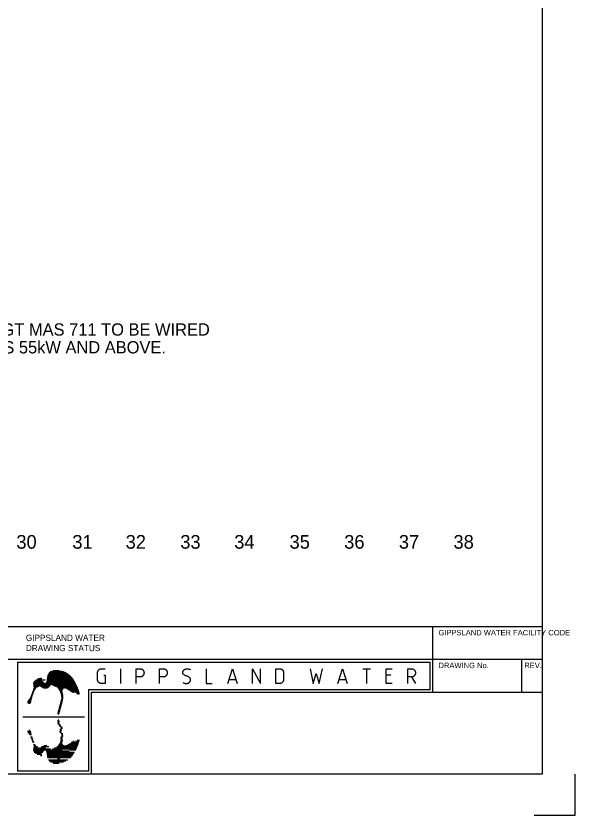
# Model space of a CAD drawing. Extents: x 0 to 841, y 0 to 594.
# Drawn here: x 636.4 to 841, y 0 to 292.5 of the extents above; entities that cross this region are included whole.
import ezdxf

# ---------------------------------------------------------------- set-up
doc = ezdxf.new("R2010")
doc.units = 0
doc.layers.add('A1BORDER', color=7, linetype='Continuous')
doc.layers.add('Level 1', color=7, linetype='Continuous')

msp = doc.modelspace()

# ---------------------------------------------------------------- linework, layer by layer
at = {"layer": 'A1BORDER'}
for p, q in [((829, 581), (829, 15)), ((592.5, 69), (829, 69)), ((789, 45), (789, 69)), ((28, 57), (829, 57)), ((637, 56), (788, 56)), ((637, 56), (637, 16)), ((788, 46), (788, 56)), ((821.5, 45), (821.5, 57)), ((649.39, 52.72), (653.15, 52.72)), ((650.01, 52.92), (652.2, 52.92)), ((644.54, 49.92), (645.36, 49.92)), ((645.37, 50.12), (645.86, 50.12)), ((647.75, 49.92), (657.17, 49.92)), ((647.78, 50.12), (657.02, 50.12)), ((647.81, 50.32), (656.86, 50.32)), ((647.85, 50.52), (656.69, 50.52)), ((647.88, 50.72), (656.5, 50.72)), ((647.91, 50.92), (656.3, 50.92)), ((647.96, 51.12), (656.08, 51.12)), ((648.03, 51.32), (655.85, 51.32)), ((648.12, 51.52), (655.59, 51.52)), ((648.23, 51.72), (655.31, 51.72)), ((648.37, 51.92), (655, 51.92)), ((648.53, 52.12), (654.64, 52.12)), ((648.74, 52.32), (654.24, 52.32)), ((649.02, 52.52), (653.76, 52.52)), ((642.73, 48.12), (658.25, 48.12)), ((642.74, 47.92), (658.35, 47.92)), ((642.75, 48.32), (646.79, 48.32)), ((642.79, 47.72), (649.08, 47.72)), ((642.81, 48.52), (646.55, 48.52)), ((642.83, 47.52), (648.95, 47.52)), ((642.85, 47.31), (644.88, 47.31)), ((642.87, 47.12), (644.57, 47.12)), ((642.88, 46.92), (644.23, 46.92)), ((642.9, 48.72), (646.37, 48.72)), ((643.04, 48.92), (646.16, 48.92)), ((643.26, 49.12), (645.9, 49.12)), ((643.54, 49.32), (645.57, 49.32)), ((643.85, 49.52), (647.09, 49.52)), ((644.18, 49.72), (645.89, 49.72)), ((645.14, 47.31), (648.83, 47.31)), ((645.49, 47.12), (648.67, 47.12)), ((645.76, 46.92), (648.42, 46.92)), ((647.19, 48.32), (658.14, 48.32)), ((647.42, 48.52), (658.03, 48.52)), ((647.54, 48.72), (657.92, 48.72)), ((647.61, 48.92), (657.8, 48.92)), ((647.63, 49.12), (657.68, 49.12)), ((647.66, 49.32), (657.57, 49.32)), ((647.69, 49.52), (657.44, 49.52)), ((647.71, 49.72), (657.31, 49.72)), ((649.72, 47.72), (658.45, 47.72)), ((650.12, 47.52), (658.55, 47.52)), ((650.48, 47.31), (658.64, 47.31)), ((650.87, 47.12), (658.73, 47.12)), ((651.36, 46.92), (658.82, 46.92)), ((641.99, 43.92), (642.48, 43.92)), ((642.06, 44.12), (642.55, 44.12)), ((642.13, 44.32), (642.62, 44.32)), ((642.21, 44.52), (642.69, 44.52)), ((642.28, 44.72), (642.76, 44.72)), ((642.35, 44.92), (642.83, 44.92)), ((642.43, 45.12), (642.9, 45.12)), ((642.5, 45.32), (643, 45.32)), ((642.57, 45.52), (643.1, 45.52)), ((642.65, 45.72), (643.2, 45.72)), ((642.72, 45.92), (643.3, 45.92)), ((642.79, 46.12), (643.4, 46.12)), ((642.84, 46.32), (643.5, 46.32)), ((642.87, 46.52), (643.6, 46.52)), ((642.88, 46.72), (643.83, 46.72)), ((646.05, 46.72), (648.11, 46.72)), ((646.62, 46.52), (647.67, 46.52)), ((651.76, 46.72), (658.9, 46.72)), ((651.88, 46.52), (654.15, 46.52)), ((651.99, 46.32), (653.71, 46.32)), ((652.1, 46.12), (653.52, 46.12)), ((652.2, 45.92), (653.4, 45.92)), ((652.31, 45.72), (653.33, 45.72)), ((652.41, 45.52), (653.31, 45.52)), ((652.5, 45.32), (653.34, 45.32)), ((652.6, 45.12), (653.38, 45.12)), ((652.69, 44.92), (653.41, 44.92)), ((652.78, 44.72), (653.44, 44.72)), ((652.83, 44.52), (653.48, 44.52)), ((652.86, 44.32), (653.53, 44.32)), ((652.89, 44.12), (653.57, 44.12)), ((652.91, 43.92), (653.62, 43.92)), ((654.57, 46.52), (658.99, 46.52)), ((655, 46.32), (659.07, 46.32)), ((655.31, 46.12), (659.14, 46.12)), ((655.62, 45.92), (659.22, 45.92)), ((655.93, 45.72), (659.29, 45.72)), ((656.24, 45.52), (659.35, 45.52)), ((656.55, 45.32), (659.42, 45.32)), ((656.86, 45.12), (657.74, 45.12)), ((657.17, 44.92), (657.68, 44.92)), ((657.51, 44.72), (657.54, 44.72)), ((657.91, 45.12), (659.48, 45.12)), ((658.19, 44.92), (659.54, 44.92)), ((658.47, 44.72), (659.59, 44.72)), ((658.75, 44.52), (659.58, 44.52)), ((659.02, 44.32), (659.47, 44.32)), ((663, 46), (788, 46)), ((663, 16), (663, 46)), ((664, 45), (829, 45)), ((664, 15), (664, 45)), ((640.62, 41.32), (641.88, 41.32)), ((640.63, 41.52), (641.93, 41.52)), ((640.72, 41.12), (641.73, 41.12)), ((640.73, 41.72), (641.95, 41.72)), ((640.9, 41.92), (641.97, 41.92)), ((641.1, 42.12), (642, 42.12)), ((641.25, 42.31), (642.04, 42.31)), ((641.37, 42.52), (642.09, 42.52)), ((641.46, 42.72), (642.15, 42.72)), ((641.55, 42.92), (642.2, 42.92)), ((641.64, 43.12), (642.25, 43.12)), ((641.73, 43.32), (642.3, 43.32)), ((641.82, 43.51), (642.35, 43.51)), ((641.91, 43.72), (642.41, 43.72)), ((652.63, 41.12), (653.26, 41.12)), ((652.68, 41.32), (653.31, 41.32)), ((652.74, 41.52), (653.37, 41.52)), ((652.79, 41.72), (653.41, 41.72)), ((652.85, 41.92), (653.45, 41.92)), ((652.9, 42.12), (653.49, 42.12)), ((652.94, 43.72), (653.67, 43.72)), ((652.95, 42.31), (653.53, 42.31)), ((652.97, 43.51), (653.71, 43.51)), ((652.99, 42.52), (653.57, 42.52)), ((653, 43.32), (653.69, 43.32)), ((653.02, 43.12), (653.67, 43.12)), ((653.03, 42.72), (653.61, 42.72)), ((653.05, 42.92), (653.64, 42.92)), ((641.03, 40.92), (641.43, 40.92)), ((651.82, 38.12), (652.44, 38.12)), ((651.87, 38.32), (652.5, 38.32)), ((651.92, 38.52), (652.55, 38.52)), ((651.98, 38.72), (652.61, 38.72)), ((652.03, 38.92), (652.66, 38.92)), ((652.09, 39.12), (652.72, 39.12)), ((652.14, 39.32), (652.77, 39.32)), ((652.2, 39.52), (652.82, 39.52)), ((652.25, 39.72), (652.88, 39.72)), ((652.3, 39.92), (652.93, 39.92)), ((652.36, 40.12), (652.99, 40.12)), ((652.41, 40.32), (653.04, 40.32)), ((652.47, 40.52), (653.1, 40.52)), ((652.52, 40.72), (653.15, 40.72)), ((652.57, 40.92), (653.2, 40.92)), ((638.93, 35.98), (661.47, 35.98)), ((651.63, 37.32), (652.23, 37.32)), ((651.64, 37.12), (652.17, 37.12)), ((651.65, 37.52), (652.28, 37.52)), ((651.71, 37.72), (652.34, 37.72)), ((651.76, 37.92), (652.39, 37.92)), ((651.79, 36.92), (651.9, 36.92)), ((651.54, 33.84), (652.17, 33.84)), ((651.63, 34.64), (652.23, 34.64)), ((651.65, 33.44), (652.28, 33.44)), ((651.71, 34.24), (652.34, 34.24)), ((651.79, 35.04), (651.9, 35.04)), ((652.03, 33.04), (652.66, 33.04)), ((652.14, 32.64), (652.77, 32.64)), ((652.66, 32.24), (653.29, 32.24)), ((640.62, 30.64), (641.88, 30.64)), ((640.73, 30.24), (641.95, 30.24)), ((641.03, 31.04), (641.43, 31.04)), ((641.1, 29.84), (642, 29.84)), ((641.37, 29.44), (642.09, 29.44)), ((652.34, 30.64), (652.97, 30.64)), ((652.45, 30.24), (653.07, 30.24)), ((652.47, 31.44), (653.1, 31.44)), ((652.57, 31.04), (653.2, 31.04)), ((652.77, 31.84), (653.4, 31.84)), ((652.9, 29.84), (653.49, 29.84)), ((652.99, 29.44), (653.57, 29.44)), ((641.73, 28.64), (642.3, 28.64)), ((641.91, 28.24), (642.41, 28.24)), ((642.06, 27.84), (642.55, 27.84)), ((642.21, 27.44), (642.69, 27.44)), ((642.35, 27.04), (642.83, 27.04)), ((642.5, 26.64), (643, 26.64)), ((652.5, 26.64), (653.34, 26.64)), ((652.66, 27.84), (653.35, 27.84)), ((652.69, 27.04), (653.41, 27.04)), ((652.72, 28.24), (653.44, 28.24)), ((652.77, 28.64), (653.46, 28.64)), ((652.83, 27.44), (653.48, 27.44)), ((653.05, 29.04), (653.64, 29.04)), ((656.55, 26.64), (659.42, 26.64)), ((657.17, 27.04), (657.68, 27.04)), ((658.19, 27.04), (659.54, 27.04)), ((658.75, 27.44), (659.58, 27.44)), ((642.73, 23.84), (653.27, 23.84)), ((642.79, 25.84), (643.4, 25.84)), ((642.79, 24.24), (649.08, 24.24)), ((642.81, 23.44), (646.55, 23.44)), ((642.85, 24.65), (644.88, 24.65)), ((642.87, 25.44), (643.6, 25.44)), ((642.88, 25.04), (644.23, 25.04)), ((645.14, 24.65), (647.18, 24.65)), ((645.76, 25.04), (648.42, 25.04)), ((646.62, 25.44), (647.67, 25.44)), ((647.42, 23.44), (655.89, 23.44)), ((649.72, 24.24), (658.45, 24.24)), ((650.48, 24.65), (658.64, 24.65)), ((651.36, 25.04), (658.82, 25.04)), ((651.88, 25.44), (654.15, 25.44)), ((652.1, 25.84), (653.52, 25.84)), ((652.31, 26.24), (653.33, 26.24)), ((654.57, 25.44), (658.99, 25.44)), ((655.31, 25.84), (659.14, 25.84)), ((655.93, 26.24), (659.29, 26.24)), ((655.94, 23.84), (658.25, 23.84)), ((643.04, 23.04), (646.16, 23.04)), ((643.54, 22.64), (645.57, 22.64)), ((644.18, 22.24), (645.89, 22.24)), ((645.37, 21.84), (645.86, 21.84)), ((647.61, 23.04), (657.8, 23.04)), ((647.66, 22.64), (657.57, 22.64)), ((647.71, 22.24), (657.31, 22.24)), ((647.78, 21.84), (657.02, 21.84)), ((647.85, 21.44), (656.69, 21.44)), ((647.91, 21.04), (656.3, 21.04)), ((651.57, 20.64), (652.44, 20.64)), ((648.23, 20.24), (655.31, 20.24)), ((648.53, 19.84), (654.64, 19.84)), ((649.02, 19.44), (653.76, 19.44)), ((650.01, 19.04), (652.2, 19.04)), ((829, 15), (28, 15)), ((663, 16), (637, 16)), ((829, 15), (829, 15)), ((841, 0), (841, 15)), ((826, 0), (841, 0))]:
    msp.add_line(p, q, dxfattribs=at)
for points in [[(668.49, 51.15), (669.06, 51.15), (669.06, 48.16), (667.64, 48.16), (667.51, 48.16), (667.39, 48.18), (667.28, 48.21), (667.15, 48.25), (667.04, 48.3), (666.93, 48.36), (666.82, 48.43), (666.73, 48.51), (666.64, 48.6), (666.55, 48.7), (666.48, 48.8), (666.41, 48.91), (666.35, 49.02), (666.31, 49.14), (666.27, 49.27), (666.24, 49.39), (666.22, 49.52), (666.22, 49.66), (666.22, 52.05), (666.22, 52.18), (666.24, 52.31), (666.27, 52.43), (666.31, 52.56), (666.35, 52.67), (666.41, 52.79), (666.48, 52.9), (666.55, 53), (666.64, 53.1), (666.73, 53.19), (666.82, 53.27), (666.93, 53.34), (667.04, 53.4), (667.15, 53.45), (667.28, 53.49), (667.39, 53.52), (667.51, 53.54), (667.64, 53.54), (669.06, 53.54)], [(674.74, 48.16), (674.74, 53.54)], [(680.42, 48.16), (680.42, 53.54), (681.84, 53.54), (681.96, 53.54), (682.08, 53.52), (682.2, 53.49), (682.32, 53.45), (682.43, 53.4), (682.54, 53.34), (682.65, 53.27), (682.74, 53.19), (682.84, 53.1), (682.92, 53), (682.99, 52.9), (683.06, 52.79), (683.12, 52.67), (683.17, 52.56), (683.21, 52.43), (683.23, 52.31), (683.25, 52.18), (683.26, 52.05), (683.25, 51.91), (683.23, 51.78), (683.21, 51.66), (683.17, 51.53), (683.12, 51.42), (683.06, 51.3), (682.99, 51.19), (682.92, 51.09), (682.84, 50.99), (682.74, 50.9), (682.65, 50.82), (682.54, 50.75), (682.43, 50.69), (682.32, 50.64), (682.2, 50.6), (682.08, 50.57), (681.96, 50.55), (681.84, 50.55), (680.42, 50.55)], [(688.93, 48.16), (688.93, 53.54), (690.35, 53.54), (690.47, 53.54), (690.59, 53.52), (690.71, 53.49), (690.83, 53.45), (690.94, 53.4), (691.05, 53.34), (691.16, 53.27), (691.26, 53.19), (691.35, 53.1), (691.43, 53), (691.51, 52.9), (691.57, 52.79), (691.63, 52.67), (691.68, 52.56), (691.72, 52.43), (691.75, 52.31), (691.76, 52.18), (691.77, 52.05), (691.76, 51.91), (691.75, 51.78), (691.72, 51.66), (691.68, 51.53), (691.63, 51.42), (691.57, 51.3), (691.51, 51.19), (691.43, 51.09), (691.35, 50.99), (691.26, 50.9), (691.16, 50.82), (691.05, 50.75), (690.94, 50.69), (690.83, 50.64), (690.71, 50.6), (690.59, 50.57), (690.47, 50.55), (690.35, 50.55), (688.93, 50.55)], [(697.45, 48.46), (697.67, 48.36), (697.9, 48.27), (698.12, 48.21), (698.36, 48.17), (698.6, 48.16), (698.84, 48.16), (698.87, 48.16), (699.03, 48.18), (699.18, 48.21), (699.33, 48.26), (699.48, 48.32), (699.62, 48.4), (699.72, 48.46), (699.81, 48.53), (699.9, 48.61), (699.98, 48.69), (700.05, 48.78), (700.11, 48.88), (700.17, 48.99), (700.22, 49.09), (700.25, 49.21), (700.28, 49.32), (700.29, 49.36), (700.3, 49.44), (700.3, 49.52), (700.3, 49.61), (700.29, 49.69), (700.27, 49.77), (700.25, 49.86), (700.22, 49.93), (700.18, 50.01), (700.14, 50.09), (700.09, 50.15), (700.04, 50.21), (700.01, 50.25), (699.85, 50.39), (699.69, 50.51), (699.52, 50.61), (699.34, 50.7), (699.15, 50.78), (698.95, 50.83), (698.87, 50.85), (698.68, 50.9), (698.49, 50.96), (698.3, 51.04), (698.12, 51.14), (697.96, 51.26), (697.8, 51.39), (697.73, 51.45), (697.67, 51.51), (697.62, 51.57), (697.58, 51.64), (697.53, 51.71), (697.5, 51.79), (697.47, 51.87), (697.46, 51.95), (697.44, 52.04), (697.43, 52.12), (697.43, 52.21), (697.44, 52.29), (697.45, 52.35), (697.47, 52.46), (697.51, 52.58), (697.55, 52.69), (697.61, 52.79), (697.67, 52.89), (697.74, 52.99), (697.82, 53.07), (697.9, 53.15), (697.99, 53.23), (698.02, 53.24), (698.15, 53.33), (698.3, 53.4), (698.44, 53.45), (698.6, 53.5), (698.75, 53.52), (698.87, 53.54), (699.11, 53.55), (699.35, 53.53), (699.58, 53.49), (699.82, 53.43), (700.04, 53.35), (700.27, 53.25)], [(705.96, 53.54), (705.96, 48.16), (708.23, 48.16)], [(713.91, 48.16), (715.61, 53.54), (717.32, 48.16)], [(722.99, 48.16), (722.99, 53.54), (725.83, 48.16), (725.83, 53.54)], [(731.52, 48.16), (731.52, 53.54), (732.94, 53.54), (733.06, 53.54), (733.18, 53.52), (733.3, 53.49), (733.42, 53.45), (733.53, 53.4), (733.64, 53.34), (733.75, 53.27), (733.84, 53.19), (733.94, 53.1), (734.02, 53), (734.09, 52.9), (734.16, 52.79), (734.22, 52.67), (734.27, 52.56), (734.31, 52.43), (734.33, 52.31), (734.35, 52.18), (734.36, 52.05), (734.36, 49.66), (734.35, 49.52), (734.33, 49.39), (734.31, 49.27), (734.27, 49.14), (734.22, 49.02), (734.16, 48.91), (734.09, 48.8), (734.02, 48.7), (733.94, 48.6), (733.84, 48.51), (733.75, 48.43), (733.64, 48.36), (733.53, 48.3), (733.42, 48.25), (733.3, 48.21), (733.18, 48.18), (733.06, 48.16), (732.94, 48.16), (731.52, 48.16)], [(744.01, 53.54), (745.14, 48.16), (746.28, 51.75), (747.41, 48.16), (748.55, 53.54)], [(754.22, 48.16), (755.92, 53.54), (757.63, 48.16)], [(763.31, 53.54), (766.15, 53.54)], [(764.73, 53.54), (764.73, 48.16)], [(774.09, 48.16), (771.82, 48.16), (771.82, 53.54), (774.09, 53.54)], [(779.78, 48.16), (779.78, 53.54), (781.2, 53.54), (781.32, 53.54), (781.44, 53.52), (781.56, 53.49), (781.68, 53.45), (781.79, 53.4), (781.9, 53.34), (782.01, 53.27), (782.1, 53.19), (782.2, 53.1), (782.28, 53), (782.35, 52.9), (782.42, 52.79), (782.48, 52.67), (782.53, 52.56), (782.56, 52.43), (782.59, 52.31), (782.61, 52.18), (782.61, 52.05), (782.61, 51.91), (782.59, 51.78), (782.56, 51.66), (782.53, 51.53), (782.48, 51.42), (782.42, 51.3), (782.35, 51.19), (782.28, 51.09), (782.2, 50.99), (782.1, 50.9), (782.01, 50.82), (781.9, 50.75), (781.79, 50.69), (781.68, 50.64), (781.56, 50.6), (781.44, 50.57), (781.32, 50.55), (781.2, 50.55), (779.78, 50.55)], [(773.53, 51.15), (771.82, 51.15)], [(781.2, 50.55), (782.61, 48.16)], [(714.48, 49.66), (716.75, 49.66)], [(754.79, 49.66), (757.06, 49.66)]]:
    msp.add_lwpolyline(points, dxfattribs=at)

# ---------------------------------------------------------------- texts
for s, height, p in [('GIPPSLAND WATER FACILITY CODE', 2, (791.03, 65.77)), ('GIPPSLAND WATER', 2.25, (640, 63.75)), ('DRAWING STATUS', 2.25, (640, 60)), ('DRAWING No.', 2, (791.03, 53.77)), ('REV.', 2, (822.43, 53.77))]:
    msp.add_text(s, height=height, dxfattribs=at).set_placement(p)
at = {"layer": 'Level 1'}
for s, height, p in [('NOTE: FLYGT MAS 711 TO BE WIRED', 4.5, (600, 175.5)), ('FOR PUMPS 55kW AND ABOVE.', 4.5, (600, 168.99)), ('30', 5, (636.52, 97.5)), ('31', 5, (657.01, 97.5)), ('32', 5, (676.52, 97.5)), ('33', 5, (696.52, 97.5)), ('34', 5, (716.27, 97.5)), ('35', 5, (736.52, 97.5)), ('36', 5, (756.52, 97.5)), ('37', 5, (776.52, 97.5)), ('38', 5, (796.52, 97.5))]:
    msp.add_text(s, height=height, dxfattribs=at).set_placement(p)

doc.saveas('drawing.dxf')
